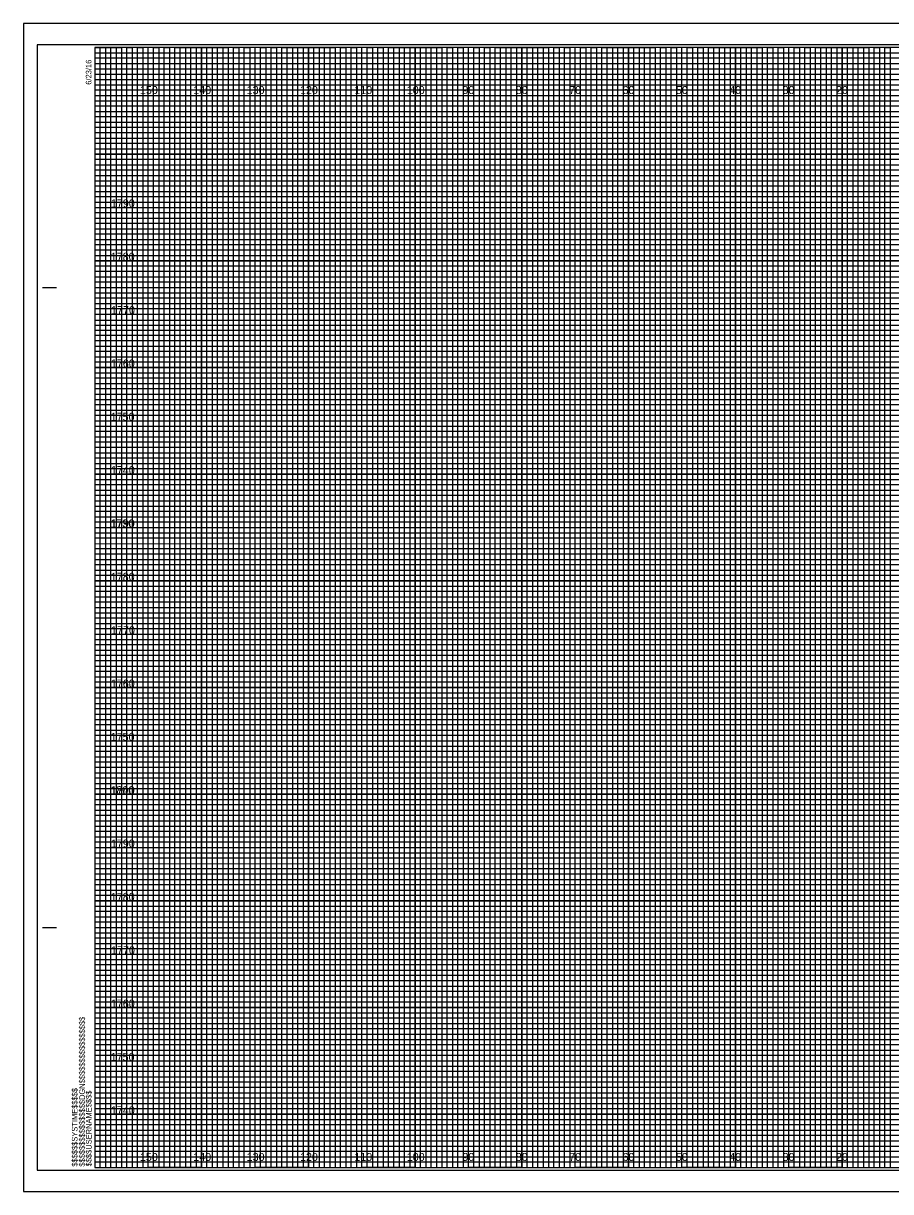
# Model space of a CAD drawing. Extents: x -15 to 323, y -5 to 6170.
# Drawn here: x -13.4 to 149.1, y 3735.5 to 3954.5 of the extents above; entities that cross this region are included whole.
import ezdxf

# ---------------------------------------------------------------- set-up
doc = ezdxf.new("R2010")
doc.units = 0
for name, color, linetype in [('Prop XS DDE', 7, 'Continuous'), ('Prop XS DDE Slope Text', 7, 'Continuous'), ('Prop XS DDE Text', 7, 'Continuous'), ('Prop XS Earthwork Shape', 7, 'Continuous'), ('Prop XS Noise Wall', 7, 'Continuous'), ('Prop XS Retaining Wall', 7, 'Continuous'), ('Prop XS Station Labels', 7, 'Continuous'), ('Scratch_Level_3', 7, 'Continuous'), ('Scratch_Level_7', 7, 'Continuous'), ('Scratch_Level_8', 7, 'Continuous'), ('Sheet Cross Section Grid Minor 1 CELL', 7, 'Continuous')]:
    doc.layers.add(name, color=color, linetype=linetype)

msp = doc.modelspace()

# ---------------------------------------------------------------- linework, layer by layer
at = {"layer": 'Prop XS DDE'}
msp.add_lwpolyline([(-13.4, 3735.5), (323.3, 3735.5), (323.3, 3954.5), (-13.4, 3954.5)], close=True, dxfattribs=at)
at = {"layer": 'Prop XS DDE Slope Text'}
msp.add_lwpolyline([(-10.8, 3739.5), (322.4, 3739.5), (322.4, 3950.5), (-10.8, 3950.5)], close=True, dxfattribs=at)
at = {"layer": 'Prop XS DDE Text'}
for p, q in [((10, 3740), (10, 3950)), ((20, 3740), (20, 3950)), ((30, 3740), (30, 3950)), ((40, 3740), (40, 3950)), ((50, 3740), (50, 3950)), ((60, 3740), (60, 3950)), ((70, 3740), (70, 3950)), ((80, 3740), (80, 3950)), ((90, 3740), (90, 3950)), ((100, 3740), (100, 3950)), ((110, 3740), (110, 3950)), ((120, 3740), (120, 3950)), ((130, 3740), (130, 3950)), ((140, 3740), (140, 3950)), ((0, 3940), (320, 3940)), ((0, 3930), (320, 3930)), ((0, 3920), (320, 3920)), ((0, 3910), (320, 3910)), ((0, 3900), (320, 3900)), ((0, 3890), (320, 3890)), ((0, 3880), (320, 3880)), ((0, 3870), (320, 3870)), ((0, 3860), (320, 3860)), ((0, 3850), (320, 3850)), ((0, 3840), (320, 3840)), ((0, 3830), (320, 3830)), ((0, 3820), (320, 3820)), ((0, 3810), (320, 3810)), ((0, 3800), (320, 3800)), ((0, 3790), (320, 3790)), ((0, 3780), (320, 3780)), ((0, 3770), (320, 3770)), ((0, 3760), (320, 3760)), ((0, 3750), (320, 3750))]:
    msp.add_line(p, q, dxfattribs=at)
at = {"layer": 'Prop XS Earthwork Shape'}
for p, q in [((10, 3950), (0, 3950)), ((10, 3740), (10, 3950)), ((30, 3950), (20, 3950)), ((20, 3950), (20, 3740)), ((30, 3740), (30, 3950)), ((50, 3950), (40, 3950)), ((40, 3950), (40, 3740)), ((50, 3740), (50, 3950)), ((70, 3950), (60, 3950)), ((60, 3950), (60, 3740)), ((70, 3740), (70, 3950)), ((90, 3950), (80, 3950)), ((80, 3950), (80, 3740)), ((90, 3740), (90, 3950)), ((110, 3950), (100, 3950)), ((100, 3950), (100, 3740)), ((110, 3740), (110, 3950)), ((130, 3950), (120, 3950)), ((120, 3950), (120, 3740)), ((130, 3740), (130, 3950)), ((150, 3950), (140, 3950)), ((140, 3950), (140, 3740)), ((20, 3740), (10, 3740)), ((40, 3740), (30, 3740)), ((60, 3740), (50, 3740)), ((80, 3740), (70, 3740)), ((100, 3740), (90, 3740)), ((120, 3740), (110, 3740)), ((140, 3740), (130, 3740))]:
    msp.add_line(p, q, dxfattribs=at)
for points in [[(0, 3940), (320, 3940), (320, 3930), (0, 3930)], [(0, 3920), (320, 3920), (320, 3910), (0, 3910)], [(0, 3900), (320, 3900), (320, 3890), (0, 3890)], [(0, 3880), (320, 3880), (320, 3870), (0, 3870)], [(0, 3860), (320, 3860), (320, 3850), (0, 3850)], [(0, 3840), (320, 3840), (320, 3830), (0, 3830)], [(0, 3820), (320, 3820), (320, 3810), (0, 3810)], [(0, 3800), (320, 3800), (320, 3790), (0, 3790)], [(0, 3780), (320, 3780), (320, 3770), (0, 3770)], [(0, 3760), (320, 3760), (320, 3750), (0, 3750)]]:
    msp.add_lwpolyline(points, dxfattribs=at)
at = {"layer": 'Prop XS Noise Wall'}
for p, q in [((-9.8, 3905), (-7.3, 3905)), ((-9.7, 3905), (-7.2, 3905)), ((-9.8, 3785), (-7.3, 3785)), ((-9.7, 3785), (-7.2, 3785)), ((0, 3740), (0, 3740)), ((0, 3740), (0, 3740)), ((0, 3740), (0, 3740)), ((0, 3740), (0, 3740)), ((0, 3740), (0, 3740)), ((0, 3740), (0, 3740)), ((0, 3740), (0, 3740))]:
    msp.add_line(p, q, dxfattribs=at)
msp.add_lwpolyline([(320, 3950), (0, 3950), (0, 3740), (320, 3740)], close=True, dxfattribs=at)
at = {"layer": 'Prop XS Retaining Wall'}
for points in [[(0, 3740), (1, 3740), (1, 3950), (2, 3950), (2, 3740)], [(2, 3740), (3, 3740), (3, 3950), (4, 3950), (4, 3740)], [(5, 3740), (6, 3740), (6, 3950), (7, 3950), (7, 3740)], [(7, 3740), (8, 3740), (8, 3950), (9, 3950), (9, 3740)], [(10, 3740), (11, 3740), (11, 3950), (12, 3950), (12, 3740)], [(12, 3740), (13, 3740), (13, 3950), (14, 3950), (14, 3740)], [(15, 3740), (16, 3740), (16, 3950), (17, 3950), (17, 3740)], [(17, 3740), (18, 3740), (18, 3950), (19, 3950), (19, 3740)], [(20, 3740), (21, 3740), (21, 3950), (22, 3950), (22, 3740)], [(22, 3740), (23, 3740), (23, 3950), (24, 3950), (24, 3740)], [(25, 3740), (26, 3740), (26, 3950), (27, 3950), (27, 3740)], [(27, 3740), (28, 3740), (28, 3950), (29, 3950), (29, 3740)], [(30, 3740), (31, 3740), (31, 3950), (32, 3950), (32, 3740)], [(32, 3740), (33, 3740), (33, 3950), (34, 3950), (34, 3740)], [(35, 3740), (36, 3740), (36, 3950), (37, 3950), (37, 3740)], [(37, 3740), (38, 3740), (38, 3950), (39, 3950), (39, 3740)], [(40, 3740), (41, 3740), (41, 3950), (42, 3950), (42, 3740)], [(42, 3740), (43, 3740), (43, 3950), (44, 3950), (44, 3740)], [(45, 3740), (46, 3740), (46, 3950), (47, 3950), (47, 3740)], [(47, 3740), (48, 3740), (48, 3950), (49, 3950), (49, 3740)], [(50, 3740), (51, 3740), (51, 3950), (52, 3950), (52, 3740)], [(52, 3740), (53, 3740), (53, 3950), (54, 3950), (54, 3740)], [(55, 3740), (56, 3740), (56, 3950), (57, 3950), (57, 3740)], [(57, 3740), (58, 3740), (58, 3950), (59, 3950), (59, 3740)], [(60, 3740), (61, 3740), (61, 3950), (62, 3950), (62, 3740)], [(62, 3740), (63, 3740), (63, 3950), (64, 3950), (64, 3740)], [(65, 3740), (66, 3740), (66, 3950), (67, 3950), (67, 3740)], [(67, 3740), (68, 3740), (68, 3950), (69, 3950), (69, 3740)], [(70, 3740), (71, 3740), (71, 3950), (72, 3950), (72, 3740)], [(72, 3740), (73, 3740), (73, 3950), (74, 3950), (74, 3740)], [(75, 3740), (76, 3740), (76, 3950), (77, 3950), (77, 3740)], [(77, 3740), (78, 3740), (78, 3950), (79, 3950), (79, 3740)], [(80, 3740), (81, 3740), (81, 3950), (82, 3950), (82, 3740)], [(82, 3740), (83, 3740), (83, 3950), (84, 3950), (84, 3740)], [(85, 3740), (86, 3740), (86, 3950), (87, 3950), (87, 3740)], [(87, 3740), (88, 3740), (88, 3950), (89, 3950), (89, 3740)], [(90, 3740), (91, 3740), (91, 3950), (92, 3950), (92, 3740)], [(92, 3740), (93, 3740), (93, 3950), (94, 3950), (94, 3740)], [(95, 3740), (96, 3740), (96, 3950), (97, 3950), (97, 3740)], [(97, 3740), (98, 3740), (98, 3950), (99, 3950), (99, 3740)], [(100, 3740), (101, 3740), (101, 3950), (102, 3950), (102, 3740)], [(102, 3740), (103, 3740), (103, 3950), (104, 3950), (104, 3740)], [(105, 3740), (106, 3740), (106, 3950), (107, 3950), (107, 3740)], [(107, 3740), (108, 3740), (108, 3950), (109, 3950), (109, 3740)], [(110, 3740), (111, 3740), (111, 3950), (112, 3950), (112, 3740)], [(112, 3740), (113, 3740), (113, 3950), (114, 3950), (114, 3740)], [(115, 3740), (116, 3740), (116, 3950), (117, 3950), (117, 3740)], [(117, 3740), (118, 3740), (118, 3950), (119, 3950), (119, 3740)], [(120, 3740), (121, 3740), (121, 3950), (122, 3950), (122, 3740)], [(122, 3740), (123, 3740), (123, 3950), (124, 3950), (124, 3740)], [(125, 3740), (126, 3740), (126, 3950), (127, 3950), (127, 3740)], [(127, 3740), (128, 3740), (128, 3950), (129, 3950), (129, 3740)], [(130, 3740), (131, 3740), (131, 3950), (132, 3950), (132, 3740)], [(132, 3740), (133, 3740), (133, 3950), (134, 3950), (134, 3740)], [(135, 3740), (136, 3740), (136, 3950), (137, 3950), (137, 3740)], [(137, 3740), (138, 3740), (138, 3950), (139, 3950), (139, 3740)], [(140, 3740), (141, 3740), (141, 3950), (142, 3950), (142, 3740)], [(142, 3740), (143, 3740), (143, 3950), (144, 3950), (144, 3740)], [(145, 3740), (146, 3740), (146, 3950), (147, 3950), (147, 3740)], [(147, 3740), (148, 3740), (148, 3950), (149, 3950), (149, 3740)]]:
    msp.add_lwpolyline(points, dxfattribs=at)
at = {"layer": 'Prop XS Station Labels'}
for points in [[(0, 3950), (5, 3950), (5, 3740), (15, 3740), (15, 3950), (25, 3950), (25, 3740), (35, 3740), (35, 3950), (45, 3950), (45, 3740), (55, 3740), (55, 3950), (65, 3950), (65, 3740), (75, 3740), (75, 3950), (85, 3950), (85, 3740), (95, 3740), (95, 3950), (105, 3950), (105, 3740), (115, 3740), (115, 3950), (125, 3950), (125, 3740), (135, 3740), (135, 3950), (145, 3950), (145, 3740), (155, 3740)], [(0, 3945), (275, 3945)], [(0, 3925), (320, 3925), (320, 3935), (0, 3935)], [(0, 3905), (320, 3905), (320, 3915), (0, 3915)], [(0, 3885), (320, 3885), (320, 3895), (0, 3895)], [(0, 3865), (320, 3865), (320, 3875), (0, 3875)], [(0, 3845), (320, 3845), (320, 3855), (0, 3855)], [(0, 3825), (320, 3825), (320, 3835), (0, 3835)], [(0, 3805), (320, 3805), (320, 3815), (0, 3815)], [(0, 3785), (320, 3785), (320, 3795), (0, 3795)], [(0, 3765), (320, 3765), (320, 3775), (0, 3775)], [(0, 3745), (320, 3745), (320, 3755), (0, 3755)]]:
    msp.add_lwpolyline(points, dxfattribs=at)
at = {"layer": 'Scratch_Level_7'}
for p, q in [((323.3, 3954.5), (-13.4, 3954.5)), ((-13.4, 3954.5), (-13.4, 3735.5)), ((-13.4, 3735.5), (323.3, 3735.5))]:
    msp.add_line(p, q, dxfattribs=at)
at = {"layer": 'Sheet Cross Section Grid Minor 1 CELL'}
for p, q in [((0, 3949), (260, 3949)), ((260, 3947.98), (0, 3947.98)), ((0, 3947.98), (0, 3947)), ((0, 3947), (260, 3947)), ((260, 3945.89), (0, 3945.89)), ((0, 3945.89), (0, 3944)), ((0, 3944), (320, 3944))]:
    msp.add_line(p, q, dxfattribs=at)
for points in [[(0, 3943), (270, 3943), (320, 3943), (320, 3942), (0, 3942)], [(0, 3941), (320, 3941), (320, 3939), (0, 3939)], [(0, 3938), (320, 3938), (320, 3937), (0, 3936.98)], [(0, 3936), (320, 3936), (320, 3934), (0, 3934)], [(0, 3933), (320, 3933), (320, 3932), (0, 3932)], [(0, 3931), (320, 3931), (320, 3929), (0, 3929)], [(0, 3928), (320, 3928), (320, 3927), (0, 3927)], [(0, 3926), (320, 3926), (320, 3924), (0, 3924)], [(0, 3923), (320, 3923), (320, 3922), (0, 3922)], [(0, 3921), (320, 3921), (320, 3919), (0, 3919)], [(0, 3918), (320, 3918), (320, 3917), (0, 3917)], [(0, 3916), (320, 3916), (320, 3913.95), (320, 3913), (320, 3912), (0, 3912)], [(0, 3914), (320, 3914), (320, 3913), (0, 3913)], [(0, 3911), (320, 3911), (320, 3909), (0, 3909.03)], [(0, 3909.03), (320, 3909), (320, 3908), (0, 3908)], [(0, 3907), (320, 3907), (320, 3906), (0, 3906)], [(0, 3904), (320, 3904), (320, 3903), (0, 3903)], [(0, 3902), (320, 3902), (320, 3901), (0, 3901)], [(-0.07, 3898.89), (320, 3898.89), (320, 3897.88), (-0.07, 3897.88)], [(0, 3897), (320, 3897), (320, 3896), (0, 3896)], [(0, 3894), (320, 3894), (320, 3893), (0, 3893)], [(0, 3892), (320, 3892), (320, 3891), (0, 3891)], [(0, 3889), (320, 3889), (320, 3888), (0, 3888)], [(0, 3887), (320, 3887), (320, 3886), (0, 3886)], [(0, 3884), (320, 3884), (320, 3883), (0, 3883)], [(0, 3882), (320, 3882), (320, 3881), (0, 3881)], [(0, 3879), (320, 3879), (319.99, 3877.98), (0, 3878)], [(0, 3877), (320, 3877), (320, 3876), (0, 3876)], [(0, 3874), (320, 3874), (320, 3873), (0, 3873)], [(0, 3872), (320, 3872), (320, 3871), (0, 3871)], [(0, 3869), (320, 3869), (320, 3868), (0, 3868)], [(0, 3867), (320, 3867), (320, 3866), (0, 3866)], [(0, 3864), (320, 3864), (320, 3863), (0, 3863)], [(0, 3862), (320, 3862), (320, 3861), (0, 3861)], [(0, 3859), (320, 3859), (320, 3858), (0, 3858)], [(0, 3856.99), (320.07, 3856.91), (320, 3856), (0, 3856)], [(0, 3854), (320, 3854), (320, 3853), (0, 3853)], [(0, 3852), (320, 3852), (320, 3851), (0, 3851)], [(0, 3849), (320, 3849), (320, 3848), (0, 3848)], [(0, 3847), (320, 3847), (320, 3846), (0, 3846)], [(0, 3844), (320, 3844), (320, 3843), (0, 3843)], [(0, 3842), (320, 3842), (320, 3841), (0, 3841)], [(0, 3839), (320, 3839), (320, 3838), (0, 3838)], [(0, 3837), (320, 3837), (320, 3836), (0, 3836)], [(0, 3834), (320, 3834), (320, 3833), (0, 3833)], [(0, 3832), (320, 3832), (320, 3831), (0, 3831)], [(0, 3829), (320, 3829), (320, 3828), (0, 3828)], [(0, 3827), (320, 3827), (320, 3826), (0, 3826)], [(0, 3824), (320, 3824), (320, 3823), (0, 3823)], [(0, 3822), (320, 3822), (320, 3821), (0, 3821)], [(0, 3819), (320, 3819), (319.99, 3817.98), (0, 3818)], [(0, 3817), (320, 3817), (320, 3816), (0, 3816)], [(0, 3814), (320, 3814), (320, 3813), (0, 3813)], [(0, 3812), (320, 3812), (320, 3811), (0, 3811)], [(0, 3809), (320, 3809), (320, 3808), (0, 3808)], [(0, 3807), (320, 3807), (320, 3806), (0, 3806)], [(0, 3804), (320, 3804), (320, 3803), (0, 3803)], [(0, 3802), (320, 3802), (320, 3801), (0, 3801)], [(0, 3799), (320, 3799), (320, 3798), (0, 3798)], [(0, 3796.99), (320.07, 3796.91), (320, 3796), (0, 3796)], [(0, 3794), (320, 3794), (320, 3793), (0, 3793)], [(0, 3792), (320, 3792), (320, 3791), (0, 3791)], [(0, 3789), (320, 3789), (320, 3788), (0, 3788)], [(0, 3787), (320, 3787), (320, 3786), (0, 3786)], [(0, 3784), (320, 3784), (320, 3783), (0, 3783)], [(0, 3782), (320, 3782), (320, 3781), (0, 3781)], [(0, 3779), (320, 3779), (320, 3778), (0, 3778)], [(0, 3777), (320, 3777), (320, 3776), (0, 3776)], [(0, 3774), (320, 3774), (320, 3773), (0, 3773)], [(0, 3772), (320, 3772), (320, 3771), (0, 3771)], [(0, 3769), (320, 3769), (320, 3768), (0, 3768)], [(0, 3767), (320, 3767), (320, 3766), (0, 3766)], [(0, 3764), (320, 3764), (320, 3763), (0, 3763)], [(0, 3762), (320, 3762), (320, 3761), (0, 3761)], [(0, 3759), (320, 3759), (320, 3758), (0, 3758)], [(0, 3757), (320, 3757), (320, 3756), (0, 3756)], [(0, 3754), (320, 3754), (320, 3753), (0, 3753)], [(0, 3752), (320, 3752), (320, 3751), (0, 3751)], [(0, 3749), (320, 3749), (320, 3748), (0, 3748)], [(0, 3747), (320, 3747), (320, 3746), (0, 3746)], [(0, 3744), (320, 3744), (320, 3743), (0, 3743)], [(0, 3742), (320, 3742), (320, 3741), (0, 3741)]]:
    msp.add_lwpolyline(points, dxfattribs=at)

# ---------------------------------------------------------------- texts
at = {"layer": 'Prop XS Noise Wall'}
for s, p in [('6/23/16', (-0.65, 3943)), ('$$$$$$$$$$$$$$$$DGN$$$$$$$$$$$$$$$$', (-1.88, 3740.18)), ('$$$$$$SYSTIME$$$$$', (-3.26, 3740.18)), ('$$$$USERNAME$$$$', (-0.62, 3740.23))]:
    msp.add_text(s, height=1.05, rotation=90, dxfattribs=at).set_placement(p)
at = {"layer": 'Scratch_Level_3'}
for s, p in [('1790', (3, 3920)), ('1780', (2.98, 3910)), ('1770', (3.04, 3900)), ('1760', (3, 3890)), ('1750', (2.96, 3880)), ('1740', (3, 3870)), ('1730', (2.92, 3860)), ('1790', (3, 3860)), ('1780', (2.98, 3850)), ('1770', (3.04, 3840)), ('1760', (3, 3830)), ('1750', (2.96, 3820)), ('1800', (2.92, 3810)), ('1740', (3, 3810)), ('1790', (3, 3800)), ('1780', (2.98, 3790)), ('1770', (3.04, 3780)), ('1760', (3, 3770)), ('1750', (2.96, 3760)), ('1740', (3, 3750))]:
    msp.add_text(s, height=1.5, dxfattribs=at).set_placement(p)
at = {"layer": 'Scratch_Level_8'}
for s, p in [('150', (8.44, 3941.25)), ('140', (18.44, 3941.25)), ('130', (28.44, 3941.25)), ('120', (38.44, 3941.25)), ('110', (48.62, 3941.25)), ('100', (58.44, 3941.25)), ('90', (68.86, 3941.25)), ('80', (78.86, 3941.25)), ('70', (88.86, 3941.25)), ('60', (98.86, 3941.25)), ('50', (108.86, 3941.25)), ('40', (118.86, 3941.25)), ('30', (128.86, 3941.25)), ('20', (138.86, 3941.25)), ('150', (8.44, 3741.25)), ('140', (18.44, 3741.25)), ('130', (28.44, 3741.25)), ('120', (38.44, 3741.25)), ('110', (48.62, 3741.25)), ('100', (58.44, 3741.25)), ('90', (68.86, 3741.25)), ('80', (78.86, 3741.25)), ('70', (88.86, 3741.25)), ('60', (98.86, 3741.25)), ('50', (108.86, 3741.25)), ('40', (118.86, 3741.25)), ('30', (128.86, 3741.25)), ('20', (138.86, 3741.25))]:
    msp.add_text(s, height=1.5, dxfattribs=at).set_placement(p)

doc.saveas('drawing.dxf')
